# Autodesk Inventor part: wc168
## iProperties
Shininess: 64.0
Length Units: 11272
Angle Units: 11279
Time Units: 11290
Mass Units: 11286
Length Display Precision: 3
Angle Display Precision: 2
Compacted: True
Part Number: wc168
Document SubType Name: Modeling
Created: 2004-08
Designer: John Blackburn
Manufacturer: Standard
Standards Organization: Custom
Material: Phenolic
Density: 0.0
Volumn: 0.0
Area: 0.0
PropertySet Name: Model Information
Control State: 0
Master: False
Checked Out: False
Author: John Blackburn
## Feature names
1. Revolution1
